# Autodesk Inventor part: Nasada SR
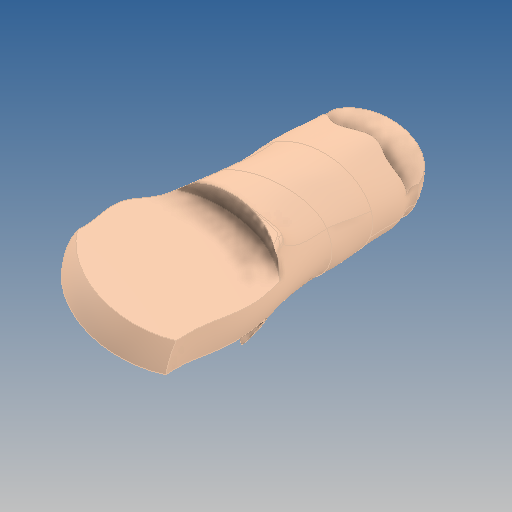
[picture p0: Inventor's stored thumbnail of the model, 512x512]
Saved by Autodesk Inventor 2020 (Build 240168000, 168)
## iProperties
Created: 2019-10
Part Number: Nasada SR
Material: GFRP
Document SubType Name: Modeling
Designer: yello
Density: 1.75 g/cm^3
Appearance: Default
Author: yello
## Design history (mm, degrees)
feature "Nasada SR"
body "Solid1"
